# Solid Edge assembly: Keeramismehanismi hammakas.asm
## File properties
Author: Türk
Template: Iso Assembly.asm
Last saved by: Türk
Revision: 9
Application: Solid Edge
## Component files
Korpus.par
Topelt hammaks.asm
16X hammasratas.par
40X hammasratas2.par
korpusekaas.par
Liigend.par
Keeramisvarras.par
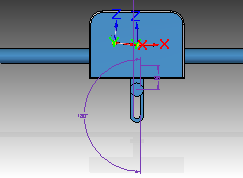
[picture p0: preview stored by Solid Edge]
